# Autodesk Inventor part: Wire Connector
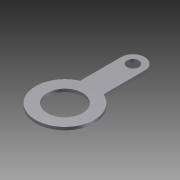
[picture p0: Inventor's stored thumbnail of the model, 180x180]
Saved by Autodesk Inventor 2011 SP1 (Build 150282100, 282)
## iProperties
Created: 2011-10
Part Number: Wire Connector
Document SubType Name: Modeling
Designer: sdarley
Density: 1 g/cm^3
Author: sdarley
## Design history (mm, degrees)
sketch "Sketch1"
  geometry: C1 r 2 at (0, 0) reference; C2 r 3 at (0, 0); C3 r 5 at (0, 0); 1 further point
  constraints: 2 centre point, 2 coincident
  dimensions: "d0" = 6 diameter of C2; "d1" = 10 diameter of C3
extrude "Extrusion1" new body sketch "Sketch1" distance "d2" = 0.5; taper "d3" = 0 deg
sketch "Sketch2"
  geometry: L1 (-2, 4.583)-(-2, 11.601); L2 (2, 4.583)-(2, 11.601); C1 r 3 at (0, 0) reference; C2 r 1 at (0, 11.601); A1 r 5 centre (0, 0) between (-2, 4.583) and (2, 4.583) reference; A2 r 2 centre (0, 11.601) between (2, 11.601) and (-2, 11.601)
  constraints: 4 end point, 4 point on circle, 2 centre point, 1 coincident, 1 parallel, 1 vertical
  dimensions: "d4" = 4 distance between parallel lines of L2 L1; "d5" = 2 distance from line of L2 C1.centre; "d6" = 2 diameter of C2
extrude "Extrusion2" join sketch "Sketch2" distance "d7" = 0.5; taper "d8" = 0 deg
body "Solid1"
node "Reference1"
